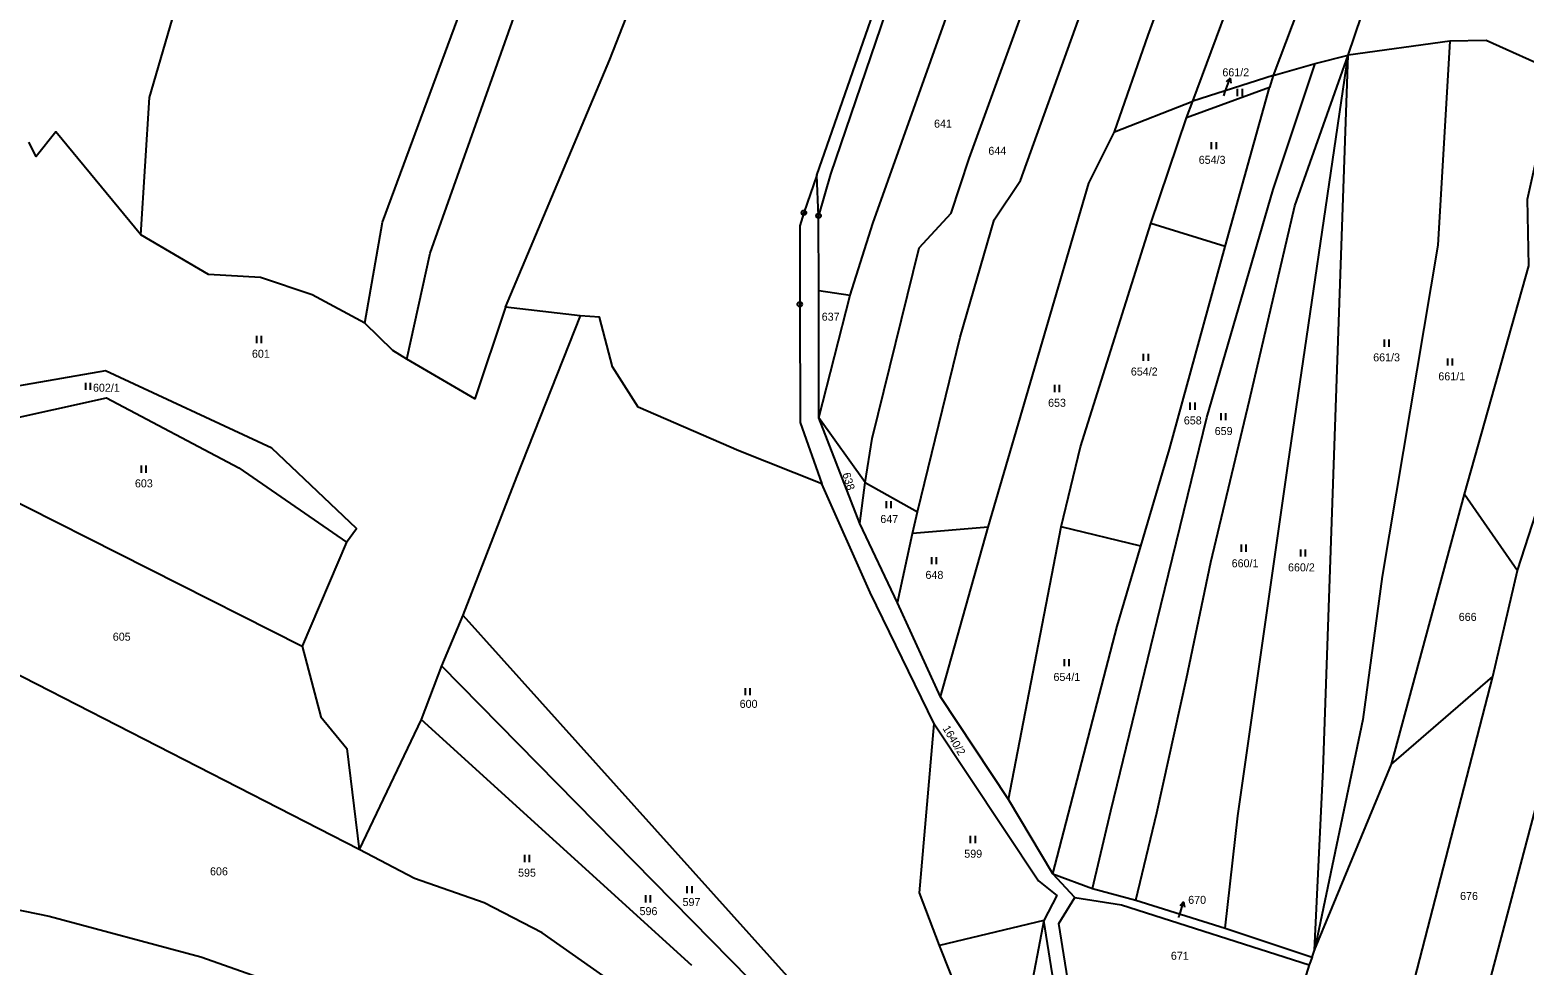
# Model space of a CAD drawing. Extents: x -680203 to -673936, y -1102717 to -1093650.
# Drawn here: x -678012.6 to -677695.3, y -1099936.9 to -1099738.1 of the extents above; entities that cross this region are included whole.
import ezdxf

# ---------------------------------------------------------------- set-up
doc = ezdxf.new("R2010")
doc.units = 0
for name, color, linetype in [('_Ideová část', 7, 'Continuous'), ('SOxx02xx_Koleje_param další_Popis10', 7, 'Continuous'), ('SOxx02xx_Staničení_Popis10', 7, 'Continuous'), ('SOxxxxxx_Koleje_hlavní_body_Popis10', 7, 'Continuous'), ('SOxxxxxx_Osa_bod_P', 7, 'Continuous'), ('x_prac', 7, 'Continuous')]:
    doc.layers.add(name, color=color, linetype=linetype)

msp = doc.modelspace()

# ---------------------------------------------------------------- linework, layer by layer
at = {"layer": '_Ideová část'}
msp.add_circle((-676417.7, -1099401.52), 1287.12, dxfattribs=at)
at = {"layer": 'SOxx02xx_Koleje_param další_Popis10'}
for centre, radius in [((-677848.22, -1099777), 0.5), ((-677848.22, -1099777), 0.0303), ((-677845.11, -1099777.63), 0.5), ((-677845.11, -1099777.63), 0.0303), ((-677849.1, -1099796.46), 0.5), ((-677849.1, -1099796.46), 0.0303)]:
    msp.add_circle(centre, radius, dxfattribs=at)
at = {"layer": 'SOxx02xx_Staničení_Popis10'}
for p, q in [((-677758.72, -1099751.21), (-677757.69, -1099748.39)), ((-677757.69, -1099748.39), (-677758.51, -1099749.16)), ((-677757.69, -1099748.39), (-677757.57, -1099749.5)), ((-677759.06, -1099752.16), (-677758.72, -1099751.21)), ((-677768.48, -1099926.29), (-677767.6, -1099923.42)), ((-677767.6, -1099923.42), (-677768.37, -1099924.23)), ((-677767.6, -1099923.42), (-677767.42, -1099924.52)), ((-677768.63, -1099926.77), (-677768.48, -1099926.29))]:
    msp.add_line(p, q, dxfattribs=at)
at = {"layer": 'SOxxxxxx_Koleje_hlavní_body_Popis10'}
for p, q in [((-677756.1, -1099752.21), (-677756.1, -1099750.71)), ((-677755.1, -1099752.21), (-677755.1, -1099750.71)), ((-677761.62, -1099763.49), (-677761.62, -1099761.99)), ((-677760.62, -1099763.49), (-677760.62, -1099761.99)), ((-677964.43, -1099804.69), (-677964.43, -1099803.19)), ((-677963.43, -1099804.69), (-677963.43, -1099803.19)), ((-677724.92, -1099805.46), (-677724.92, -1099803.96)), ((-677723.92, -1099805.46), (-677723.92, -1099803.96)), ((-677776.06, -1099808.47), (-677776.06, -1099806.97)), ((-677775.06, -1099808.47), (-677775.06, -1099806.97)), ((-677711.47, -1099809.49), (-677711.47, -1099807.99)), ((-677710.47, -1099809.49), (-677710.47, -1099807.99)), ((-678000.73, -1099814.61), (-678000.73, -1099813.11)), ((-677999.73, -1099814.61), (-677999.73, -1099813.11)), ((-677794.93, -1099815.1), (-677794.93, -1099813.6)), ((-677793.93, -1099815.1), (-677793.93, -1099813.6)), ((-677766.15, -1099818.85), (-677766.15, -1099817.35)), ((-677765.15, -1099818.85), (-677765.15, -1099817.35)), ((-677759.62, -1099821.1), (-677759.62, -1099819.6)), ((-677758.62, -1099821.1), (-677758.62, -1099819.6)), ((-677988.9, -1099832.23), (-677988.9, -1099830.73)), ((-677987.9, -1099832.23), (-677987.9, -1099830.73)), ((-677830.71, -1099839.79), (-677830.71, -1099838.29)), ((-677829.71, -1099839.79), (-677829.71, -1099838.29)), ((-677821.06, -1099851.68), (-677821.06, -1099850.18)), ((-677820.06, -1099851.68), (-677820.06, -1099850.18)), ((-677755.31, -1099849.02), (-677755.31, -1099847.52)), ((-677754.31, -1099849.02), (-677754.31, -1099847.52)), ((-677742.69, -1099850.07), (-677742.69, -1099848.57)), ((-677741.69, -1099850.07), (-677741.69, -1099848.57)), ((-677792.86, -1099873.35), (-677792.86, -1099871.85)), ((-677791.86, -1099873.35), (-677791.86, -1099871.85)), ((-677860.62, -1099879.48), (-677860.62, -1099877.98)), ((-677859.62, -1099879.48), (-677859.62, -1099877.98)), ((-677812.81, -1099910.92), (-677812.81, -1099909.42)), ((-677811.81, -1099910.92), (-677811.81, -1099909.42)), ((-677907.53, -1099914.95), (-677907.53, -1099913.45)), ((-677906.53, -1099914.95), (-677906.53, -1099913.45)), ((-677872.99, -1099921.6), (-677872.99, -1099920.1)), ((-677871.99, -1099921.6), (-677871.99, -1099920.1)), ((-677881.79, -1099923.53), (-677881.79, -1099922.03)), ((-677880.79, -1099923.53), (-677880.79, -1099922.03))]:
    msp.add_line(p, q, dxfattribs=at)
at = {"layer": 'x_prac'}
for p, q in [((-677732.6, -1099743.52), (-677705.41, -1099662.71)), ((-677711.02, -1099740.53), (-677732.6, -1099743.52)), ((-677748.52, -1099747.86), (-677739.6, -1099745.3)), ((-677739.6, -1099745.3), (-677732.6, -1099743.52)), ((-677748.52, -1099747.86), (-677765.63, -1099753.27)), ((-677748.52, -1099747.86), (-677749.32, -1099750.37)), ((-677749.32, -1099750.37), (-677766.98, -1099756.87)), ((-677758.78, -1099784.18), (-677749.32, -1099750.37)), ((-677782.23, -1099759.79), (-677765.63, -1099753.27)), ((-677766.98, -1099756.87), (-677765.63, -1099753.27)), ((-677774.53, -1099779.28), (-677766.98, -1099756.87)), ((-677845.11, -1099777.63), (-677845.5, -1099769)), ((-677845.08, -1099793.55), (-677845.11, -1099777.63)), ((-677758.78, -1099784.18), (-677774.53, -1099779.28)), ((-677696.66, -1099852.98), (-677675.78, -1099788.33)), ((-677845.08, -1099793.55), (-677838.4, -1099794.53)), ((-677845.05, -1099820.6), (-677845.08, -1099793.55)), ((-677845.05, -1099820.6), (-677838.4, -1099794.53)), ((-677895.71, -1099798.91), (-677911.58, -1099797.06)), ((-677836.36, -1099843.05), (-677845.05, -1099820.6)), ((-677835.18, -1099834.35), (-677845.05, -1099820.6)), ((-678028.77, -1099831.67), (-677954.79, -1099869.09)), ((-677836.36, -1099843.05), (-677835.18, -1099834.35)), ((-677835.18, -1099834.35), (-677824.13, -1099840.58)), ((-677723.44, -1099894.13), (-677707.92, -1099836.82)), ((-677707.92, -1099836.82), (-677696.66, -1099852.98)), ((-677825.19, -1099845.15), (-677824.13, -1099840.58)), ((-677828.35, -1099859.9), (-677836.36, -1099843.05)), ((-677809.1, -1099843.78), (-677825.19, -1099845.15)), ((-677819.21, -1099879.85), (-677809.1, -1099843.78)), ((-677804.8, -1099901.65), (-677793.59, -1099843.71)), ((-677776.66, -1099847.82), (-677793.59, -1099843.71)), ((-677945.37, -1099847.02), (-677954.79, -1099869.09)), ((-677828.35, -1099859.9), (-677825.19, -1099845.15)), ((-677701.89, -1099875.55), (-677696.66, -1099852.98)), ((-677819.21, -1099879.85), (-677828.35, -1099859.9)), ((-677920.69, -1099862.52), (-677925.17, -1099873.3)), ((-677920.69, -1099862.52), (-677811.6, -1099983.89)), ((-677942.7, -1099912.28), (-678028.52, -1099868.34)), ((-677925.17, -1099873.3), (-677929.48, -1099884.65)), ((-677813.57, -1099986.82), (-677925.17, -1099873.3)), ((-677723.44, -1099894.13), (-677701.89, -1099875.55)), ((-677720.79, -1099948.7), (-677701.89, -1099875.55)), ((-677804.8, -1099901.65), (-677819.21, -1099879.85)), ((-677929.48, -1099884.65), (-677942.7, -1099912.28)), ((-677872.05, -1099936.93), (-677929.48, -1099884.65)), ((-677739.76, -1099933.67), (-677723.44, -1099894.13)), ((-677795.36, -1099917.46), (-677804.8, -1099901.65)), ((-677790.7, -1099922.47), (-677795.36, -1099917.46)), ((-677795.36, -1099917.46), (-677786.9, -1099920.56)), ((-677786.9, -1099920.56), (-677777.69, -1099923.03)), ((-677777.69, -1099923.03), (-677758.73, -1099929.04)), ((-677797.24, -1099927.37), (-677819.4, -1099932.66)), ((-677797.24, -1099927.37), (-677805.15, -1099968.83)), ((-677758.73, -1099929.04), (-677740.25, -1099935.16)), ((-677805.15, -1099968.83), (-677819.4, -1099932.66)), ((-677740.25, -1099935.16), (-677740.91, -1099936.79)), ((-677740.25, -1099935.16), (-677739.76, -1099933.67)), ((-677740.91, -1099936.79), (-677745.35, -1099951.19))]:
    msp.add_line(p, q, dxfattribs=at)
for points in [[(-677989.05, -1099781.68), (-677987.18, -1099752.52), (-677978.96, -1099724.03), (-677968.24, -1099696.93), (-677952.55, -1099644.91), (-677939.11, -1099585.71), (-677934.99, -1099570.3)], [(-677941.45, -1099800.45), (-677937.74, -1099779.03), (-677908.54, -1099700.03), (-677894, -1099654.64), (-677870.4, -1099572.76)], [(-677932.54, -1099808.11), (-677927.63, -1099785.62), (-677892.4, -1099686.38), (-677857.44, -1099573.14)], [(-677911.58, -1099797.06), (-677889.41, -1099744.42), (-677865.79, -1099684.03), (-677844.66, -1099620.04), (-677846.17, -1099614.62)], [(-677845.5, -1099769), (-677813.8, -1099678.1), (-677809.59, -1099665.34), (-677802.59, -1099639.45), (-677798.73, -1099620.56)], [(-677795.43, -1099620.9), (-677799.77, -1099639.57), (-677813.92, -1099685.99), (-677822.35, -1099709.35), (-677842.56, -1099768.84), (-677845.11, -1099777.63)], [(-677782.23, -1099759.79), (-677775.07, -1099739.24), (-677748.56, -1099666.86), (-677733.85, -1099624.57)], [(-677765.63, -1099753.27), (-677739.96, -1099684.21), (-677724.97, -1099634.93)], [(-677713.88, -1099650.35), (-677726.15, -1099688.48), (-677748.52, -1099747.86)], [(-677824.13, -1099840.58), (-677815.02, -1099803.44), (-677807.83, -1099778.49), (-677802.23, -1099770.12), (-677777.71, -1099702.1)], [(-677838.4, -1099794.53), (-677833.6, -1099779.31), (-677808.97, -1099710.1)], [(-677835.18, -1099834.35), (-677833.75, -1099824.98), (-677823.75, -1099784.49), (-677816.94, -1099777.08), (-677813.14, -1099765.46), (-677794.12, -1099713.3)], [(-677711.02, -1099740.53), (-677713.6, -1099783.9), (-677725.4, -1099854.29), (-677729.52, -1099884.69), (-677739.76, -1099933.67)], [(-677688.52, -1099747.04), (-677703.33, -1099740.43), (-677711.02, -1099740.53)], [(-677786.9, -1099920.56), (-677783, -1099904.09), (-677773.2, -1099863.65), (-677762.63, -1099820.54), (-677748.58, -1099772.06), (-677739.6, -1099745.3)], [(-677777.69, -1099923.03), (-677773.29, -1099904.52), (-677766.99, -1099875.94), (-677761.8, -1099851.24), (-677753.58, -1099816.83), (-677743.95, -1099775.51), (-677732.6, -1099743.52)], [(-677758.73, -1099929.04), (-677756.03, -1099905.15), (-677745.42, -1099830.77), (-677732.6, -1099743.52)], [(-677739.76, -1099933.67), (-677737.91, -1099895.28), (-677732.6, -1099743.52)], [(-677707.92, -1099836.82), (-677694.27, -1099788.26), (-677694.57, -1099774.1), (-677688.52, -1099747.04)], [(-677989.05, -1099781.68), (-678007.12, -1099759.82), (-678011.32, -1099765.03), (-678012.84, -1099762.04)], [(-677809.1, -1099843.78), (-677787.69, -1099770.7), (-677782.23, -1099759.79)], [(-677845.5, -1099769), (-677848.22, -1099777), (-677849.08, -1099779.75), (-677849.1, -1099796.46), (-677848.99, -1099821.55), (-677844.4, -1099834.63)], [(-677793.59, -1099843.71), (-677789.49, -1099826.73), (-677774.53, -1099779.28)], [(-677941.45, -1099800.45), (-677952.64, -1099794.46), (-677963.66, -1099790.75), (-677974.68, -1099790.15), (-677989.05, -1099781.68)], [(-677776.66, -1099847.82), (-677770.59, -1099827.25), (-677758.78, -1099784.18)], [(-677911.58, -1099797.06), (-677918.12, -1099816.52), (-677932.54, -1099808.11)], [(-677895.71, -1099798.91), (-677909.24, -1099833.12), (-677920.69, -1099862.52)], [(-677844.4, -1099834.63), (-677862.07, -1099827.6), (-677883.4, -1099818.34), (-677888.9, -1099809.73), (-677891.61, -1099799.21), (-677895.71, -1099798.91)], [(-677932.54, -1099808.11), (-677935.54, -1099806.25), (-677941.45, -1099800.45)], [(-677945.37, -1099847.02), (-677943.27, -1099844.08), (-677961.2, -1099827), (-677996.57, -1099810.61), (-678032.38, -1099816.81), (-678033.93, -1099818.16)], [(-677712.67, -1099978.54), (-677678.33, -1099848.87), (-677667.92, -1099813.74)], [(-678029.37, -1099823.59), (-677996.33, -1099816.31), (-677968.22, -1099831.21), (-677945.37, -1099847.02)], [(-677820.57, -1099885.58), (-677834.15, -1099857.69), (-677844.4, -1099834.63)], [(-677795.36, -1099917.46), (-677781.7, -1099864.81), (-677776.66, -1099847.82)], [(-677954.79, -1099869.09), (-677950.8, -1099884.14), (-677945.29, -1099890.86), (-677942.7, -1099912.28)], [(-677819.4, -1099932.66), (-677823.7, -1099921.49), (-677820.57, -1099885.58)], [(-677820.57, -1099885.58), (-677798.39, -1099918.93), (-677794.48, -1099922.04), (-677797.24, -1099927.37)], [(-677880.66, -1099946.27), (-677903.81, -1099930.01), (-677916.12, -1099923.61), (-677930.96, -1099918.47), (-677942.7, -1099912.28)], [(-678040.65, -1099919.85), (-678008.56, -1099926.48), (-677976.28, -1099935.1), (-677931.37, -1099950.95), (-677865.02, -1099975.4)], [(-677791.66, -1099943.09), (-677794.06, -1099928.04), (-677790.7, -1099922.47)], [(-677790.7, -1099922.47), (-677780.8, -1099924.05), (-677740.91, -1099936.79)], [(-677810.91, -1100000.18), (-677809.11, -1099987.84), (-677803.46, -1099974.39), (-677797.59, -1099951.39), (-677794.9, -1099942.05), (-677797.24, -1099927.37)]]:
    msp.add_lwpolyline(points, dxfattribs=at)

# ---------------------------------------------------------------- texts
at = {"layer": 'SOxxxxxx_Osa_bod_P'}
for s, p in [('661/2', (-677759.34, -1099748.02)), ('641', (-677820.58, -1099758.92)), ('644', (-677809.05, -1099764.69)), ('654/3', (-677764.36, -1099766.61)), ('637', (-677844.44, -1099799.94)), ('601', (-677965.46, -1099807.81)), ('661/3', (-677727.31, -1099808.58)), ('654/2', (-677778.78, -1099811.59)), ('661/1', (-677713.47, -1099812.61)), ('602/1', (-677999.22, -1099815.03)), ('653', (-677796.36, -1099818.23)), ('658', (-677767.53, -1099821.98)), ('659', (-677760.97, -1099824.23)), ('603', (-677990.31, -1099835.35)), ('647', (-677831.99, -1099842.92)), ('660/1', (-677757.37, -1099852.33)), ('648', (-677822.4, -1099854.8)), ('660/2', (-677745.4, -1099853.2)), ('666', (-677709.14, -1099863.72)), ('605', (-677995.01, -1099867.93)), ('654/1', (-677795.21, -1099876.48)), ('600', (-677861.87, -1099882.2)), ('599', (-677814.16, -1099914.04)), ('606', (-677974.36, -1099917.78)), ('595', (-677908.93, -1099918.07)), ('597', (-677874, -1099924.31)), ('670', (-677766.6, -1099923.84)), ('676', (-677708.85, -1099923.02)), ('596', (-677883.13, -1099926.24)), ('671', (-677770.28, -1099935.73))]:
    msp.add_text(s, height=1.7, dxfattribs=at).set_placement(p)
for s, rotation, p in [('638', 287, (-677840.07, -1099832.49)), ('1640/2', 301, (-677818.84, -1099886.56))]:
    msp.add_text(s, height=1.7, rotation=rotation, dxfattribs=at).set_placement(p)

doc.saveas('drawing.dxf')
